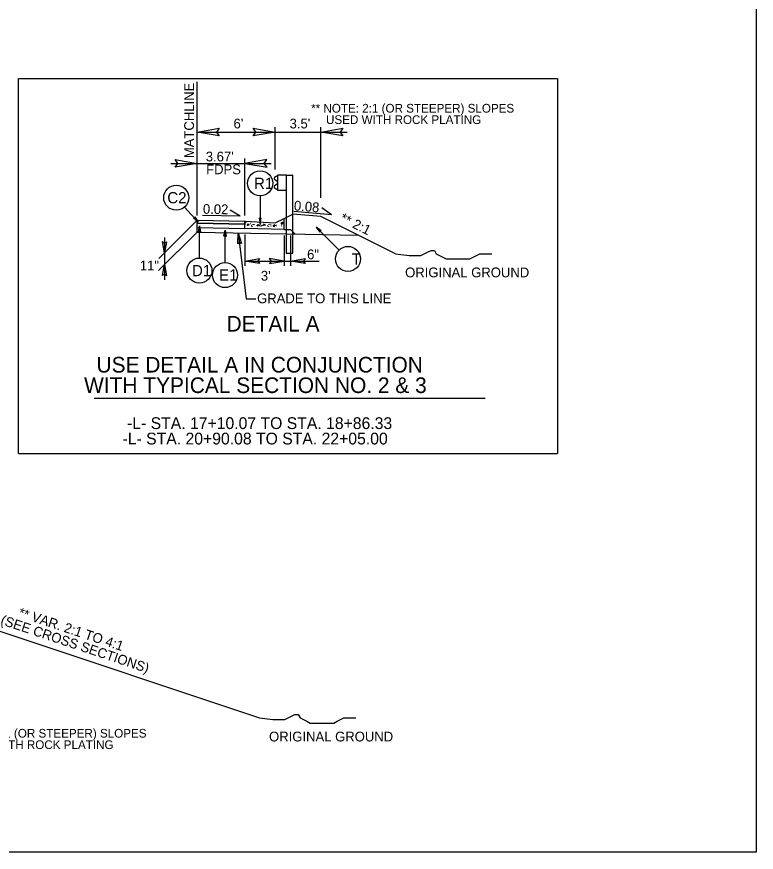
# Model space of a CAD drawing. Extents: x 1548135 to 1549339, y 868664 to 869085.
# Drawn here: x 1548249 to 1548305.7, y 868939.3 to 869003.5 of the extents above; entities that cross this region are included whole.
import ezdxf

# ---------------------------------------------------------------- set-up
doc = ezdxf.new("R2010")
doc.units = 0
for name, color, linetype in [('Default', 7, 'Continuous'), ('P_RDY_Shade_Light', 7, 'Continuous'), ('P_RDY_TC_Pvmt_Asphalt_Base_Course', 7, 'Continuous'), ('Prop Dimension', 7, 'Continuous'), ('Prop Dimension Text', 7, 'Continuous'), ('Prop Terminator CELL', 7, 'Continuous'), ('Sheet_Data_Field_CELL', 7, 'Continuous'), ('Sheet_Plan', 7, 'Continuous'), ('Typical Grade Point Symbol CELL', 7, 'Continuous'), ('Typical Hinge Slope Arterial CELL', 7, 'Continuous'), ('Typical Hinge Slope Interstate CELL', 7, 'Continuous'), ('Typical Pavement Slope Information CELL', 7, 'Continuous'), ('Typical Shoulder Slope CELL', 7, 'Continuous'), ('Typical Slope Point Local CELL', 7, 'Continuous'), ('Typical Terminator CELL', 7, 'Continuous'), ('Typical Text Centerline CELL', 7, 'Continuous'), ('Typical Text General CELL', 7, 'Continuous'), ('Typical Text Grade Point CELL', 7, 'Continuous'), ('z - Construction', 7, 'Continuous')]:
    doc.layers.add(name, color=color, linetype=linetype)

msp = doc.modelspace()

# ---------------------------------------------------------------- linework, layer by layer
at = {"layer": 'Default'}
msp.add_lwpolyline([(1548135.738, 869049.324), (1548305.738, 869049.324), (1548305.738, 868939.324), (1548135.738, 868939.324)], close=True, dxfattribs=at)
at = {"layer": 'P_RDY_Shade_Light'}
for p, q in [((1548266.481, 868987.796), (1548266.481, 868987.796)), ((1548266.481, 868987.212), (1548266.481, 868987.785)), ((1548266.492, 868987.795), (1548268.815, 868987.656)), ((1548268.815, 868987.656), (1548269.481, 868987.986)), ((1548269.481, 868987.152), (1548269.481, 868987.986)), ((1548269.481, 868987.152), (1548266.481, 868987.212)), ((1548266.659, 868987.463), (1548266.745, 868987.582)), ((1548266.78, 868987.469), (1548266.659, 868987.463)), ((1548266.745, 868987.582), (1548266.78, 868987.469)), ((1548267.425, 868987.412), (1548267.487, 868987.526)), ((1548267.59, 868987.451), (1548267.425, 868987.412)), ((1548267.487, 868987.526), (1548267.59, 868987.451)), ((1548267.909, 868987.463), (1548267.994, 868987.582)), ((1548268.029, 868987.469), (1548267.909, 868987.463)), ((1548267.994, 868987.582), (1548268.029, 868987.469)), ((1548268.673, 868987.412), (1548268.736, 868987.526)), ((1548268.839, 868987.451), (1548268.673, 868987.412)), ((1548268.736, 868987.526), (1548268.839, 868987.451)), ((1548269.251, 868987.654), (1548269.268, 868987.564)), ((1548269.405, 868987.61), (1548269.251, 868987.654)), ((1548269.268, 868987.564), (1548269.405, 868987.61))]:
    msp.add_line(p, q, dxfattribs=at)
for centre in [(1548269.377, 868987.695), (1548266.511, 868987.55), (1548266.549, 868987.675), (1548266.916, 868987.6), (1548266.976, 868987.422), (1548267.032, 868987.388), (1548267.065, 868987.515), (1548267.14, 868987.512), (1548267.191, 868987.543), (1548267.237, 868987.428), (1548267.432, 868987.467), (1548267.637, 868987.451), (1548267.654, 868987.501), (1548267.664, 868987.56), (1548267.721, 868987.417), (1548267.817, 868987.463), (1548267.911, 868987.473), (1548268.031, 868987.422), (1548268.225, 868987.422), (1548268.281, 868987.388), (1548268.314, 868987.515), (1548268.44, 868987.543), (1548268.486, 868987.428), (1548268.681, 868987.467), (1548268.709, 868987.365), (1548268.886, 868987.451), (1548268.903, 868987.501), (1548269.16, 868987.473), (1548269.28, 868987.422)]:
    msp.add_circle(centre, 0.00802, dxfattribs=at)
msp.add_arc((1548266.492, 868987.785), 0.0104, 87.95199, 180, dxfattribs=at)
at = {"layer": 'P_RDY_TC_Pvmt_Asphalt_Base_Course'}
for points in [[(1548264.499, 868994.339), (1548262.811, 868994.629), (1548264.508, 868994.929), (1548264.292, 868994.629)], [(1548267.124, 868994.92), (1548268.811, 868994.629), (1548267.114, 868994.329), (1548267.33, 868994.629)], [(1548273.999, 868994.339), (1548272.311, 868994.629), (1548274.008, 868994.929), (1548273.792, 868994.629)], [(1548261.124, 868992.513), (1548262.811, 868992.222), (1548261.114, 868991.922), (1548261.33, 868992.222)], [(1548268.169, 868992.513), (1548266.481, 868992.222), (1548268.178, 868991.922), (1548267.962, 868992.222)], [(1548267.606, 868984.526), (1548266.481, 868984.72), (1548267.612, 868984.92), (1548267.469, 868984.72)], [(1548268.356, 868984.526), (1548269.481, 868984.72), (1548268.35, 868984.92), (1548268.494, 868984.72)], [(1548271.106, 868984.526), (1548269.981, 868984.72), (1548271.112, 868984.92), (1548270.969, 868984.72)]]:
    msp.add_lwpolyline(points, close=True, dxfattribs=at)
at = {"layer": 'Prop Dimension'}
for points in [[(1548278.043, 868985.28), (1548279.08, 868985.15), (1548279.339, 868985.15), (1548279.729, 868985.15), (1548279.988, 868985.15), (1548280.248, 868985.28), (1548280.507, 868985.41), (1548280.766, 868985.54), (1548281.026, 868985.54), (1548281.156, 868985.28), (1548281.415, 868985.15), (1548281.674, 868985.02), (1548281.934, 868984.891), (1548282.193, 868984.891), (1548282.452, 868984.891), (1548282.712, 868984.891), (1548282.971, 868984.891), (1548283.23, 868984.891), (1548283.49, 868984.891), (1548283.749, 868984.891), (1548284.008, 868985.02), (1548284.268, 868985.15), (1548284.527, 868985.28), (1548284.917, 868985.28), (1548285.176, 868985.28), (1548285.435, 868985.28)], [(1548267.597, 868949.64), (1548268.635, 868949.511), (1548268.894, 868949.511), (1548269.284, 868949.511), (1548269.543, 868949.511), (1548269.802, 868949.64), (1548270.062, 868949.77), (1548270.321, 868949.9), (1548270.58, 868949.9), (1548270.71, 868949.64), (1548270.97, 868949.511), (1548271.229, 868949.381), (1548271.488, 868949.251), (1548271.748, 868949.251), (1548272.007, 868949.251), (1548272.266, 868949.251), (1548272.526, 868949.251), (1548272.785, 868949.251), (1548273.044, 868949.251), (1548273.304, 868949.251), (1548273.563, 868949.381), (1548273.822, 868949.511), (1548274.082, 868949.64), (1548274.471, 868949.64), (1548274.731, 868949.64), (1548274.99, 868949.64)]]:
    msp.add_lwpolyline(points, dxfattribs=at)
at = {"layer": 'Prop Dimension Text'}
msp.add_line((1548262.811, 868987.619), (1548266.481, 868987.546), dxfattribs=at)
at = {"layer": 'Prop Terminator CELL'}
msp.add_lwpolyline([(1548262.811, 868987.869), (1548266.481, 868987.796), (1548266.481, 868987.546), (1548262.811, 868987.619)], close=True, dxfattribs=at)
at = {"layer": 'Sheet_Data_Field_CELL'}
for p, q in [((1548269.481, 868987.986), (1548270.159, 868988.325)), ((1548278.043, 868985.28), (1548272.311, 868988.145)), ((1548238.749, 868959.256), (1548267.597, 868949.64))]:
    msp.add_line(p, q, dxfattribs=at)
at = {"layer": 'Sheet_Plan'}
msp.add_line((1548272.311, 868988.145), (1548270.159, 868988.325), dxfattribs=at)
at = {"layer": 'Typical Grade Point Symbol CELL'}
for p, q in [((1548262.811, 868988.229), (1548262.811, 868998.48)), ((1548268.811, 868991.758), (1548268.811, 868994.992)), ((1548272.311, 868989.577), (1548272.311, 868994.992)), ((1548262.811, 868994.629), (1548268.811, 868994.629)), ((1548263.811, 868994.629), (1548265.811, 868994.629)), ((1548268.811, 868994.629), (1548274.322, 868994.629)), ((1548269.811, 868994.629), (1548271.811, 868994.629)), ((1548260.801, 868992.222), (1548268.492, 868992.222)), ((1548266.481, 868988.229), (1548266.481, 868992.586)), ((1548266.481, 868986.753), (1548266.481, 868984.357)), ((1548269.481, 868986.682), (1548269.481, 868984.357)), ((1548269.981, 868986.682), (1548269.981, 868984.357)), ((1548266.481, 868984.72), (1548269.481, 868984.72)), ((1548267.462, 868984.72), (1548269.462, 868984.72)), ((1548269.481, 868984.72), (1548272.182, 868984.72))]:
    msp.add_line(p, q, dxfattribs=at)
at = {"layer": 'Typical Hinge Slope Interstate CELL'}
for p, q in [((1548267.652, 868989.728), (1548267.652, 868987.556)), ((1548261.841, 868988.861), (1548262.903, 868987.716)), ((1548259.86, 868984.918), (1548262.811, 868987.869)), ((1548262.989, 868984.952), (1548262.989, 868987.437)), ((1548264.953, 868984.605), (1548264.953, 868987.091)), ((1548273.714, 868985.564), (1548271.956, 868987.321)), ((1548259.858, 868984), (1548262.81, 868986.952)), ((1548260.306, 868986.519), (1548260.306, 868983.292)), ((1548249.097, 868969.942), (1548290.477, 868969.942))]:
    msp.add_line(p, q, dxfattribs=at)
for points in [[(1548249.097, 868969.942), (1548249.097, 868998.746), (1548290.477, 868998.746)], [(1548290.477, 868998.746), (1548290.477, 868969.942)], [(1548265.97, 868986.889), (1548266.576, 868981.812), (1548267.327, 868981.812)]]:
    msp.add_lwpolyline(points, dxfattribs=at)
for points in [[(1548262.644, 868988.114), (1548262.903, 868987.716), (1548262.521, 868988.005), (1548262.623, 868988.018)], [(1548267.571, 868988.025), (1548267.652, 868987.556), (1548267.735, 868988.027), (1548267.652, 868987.968)], [(1548262.908, 868986.969), (1548262.989, 868987.437), (1548263.072, 868986.966), (1548262.989, 868987.026)], [(1548264.872, 868986.622), (1548264.953, 868987.091), (1548265.036, 868986.619), (1548264.953, 868986.679)], [(1548272.344, 868987.047), (1548271.956, 868987.321), (1548272.23, 868986.929), (1548272.247, 868987.031)], [(1548265.926, 868986.034), (1548265.97, 868986.889), (1548266.219, 868986.065), (1548266.058, 868986.154)], [(1548260.451, 868986.208), (1548260.306, 868985.364), (1548260.156, 868986.212), (1548260.306, 868986.105)], [(1548260.161, 868983.603), (1548260.306, 868984.447), (1548260.456, 868983.599), (1548260.306, 868983.707)]]:
    msp.add_lwpolyline(points, close=True, dxfattribs=at)
for centre in [(1548267.652, 868990.69), (1548261.208, 868989.585), (1548274.393, 868984.884), (1548262.989, 868983.99), (1548264.953, 868983.644)]:
    msp.add_circle(centre, 0.962, dxfattribs=at)
at = {"layer": 'Typical Pavement Slope Information CELL'}
for p, q in [((1548266.124, 868988.16), (1548265.341, 868988.633)), ((1548273.126, 868988.28), (1548270.243, 868988.52)), ((1548273.126, 868988.28), (1548272.375, 868988.802)), ((1548266.124, 868988.16), (1548263.231, 868988.218))]:
    msp.add_line(p, q, dxfattribs=at)
at = {"layer": 'Typical Slope Point Local CELL'}
for p, q in [((1548268.887, 868991.224), (1548268.749, 868991.127)), ((1548268.75, 868990.998), (1548268.958, 868990.854)), ((1548268.987, 868991.245), (1548268.9, 868991.229)), ((1548269.659, 868991.325), (1548268.992, 868991.325)), ((1548268.992, 868991.325), (1548268.992, 868990.158)), ((1548269.659, 868991.325), (1548270.159, 868991.325)), ((1548269.675, 868991.325), (1548269.659, 868991.325)), ((1548269.659, 868991.325), (1548269.659, 868985.325)), ((1548269.675, 868985.325), (1548269.675, 868991.325)), ((1548270.159, 868991.325), (1548270.143, 868991.325)), ((1548270.143, 868991.325), (1548270.143, 868985.325)), ((1548270.159, 868985.325), (1548270.159, 868991.325)), ((1548268.749, 868990.356), (1548268.887, 868990.259)), ((1548268.958, 868990.629), (1548268.75, 868990.485)), ((1548268.992, 868990.789), (1548268.992, 868990.741)), ((1548268.992, 868990.741), (1548268.992, 868990.693)), ((1548268.9, 868990.253), (1548268.987, 868990.238)), ((1548268.992, 868990.158), (1548269.659, 868990.158)), ((1548269.659, 868985.325), (1548270.159, 868985.325)), ((1548269.659, 868985.325), (1548269.675, 868985.325)), ((1548270.143, 868985.325), (1548270.159, 868985.325))]:
    msp.add_line(p, q, dxfattribs=at)
for centre, radius, start, end in [((1548268.795, 868991.062), 0.0787, 125.2976, 235.34784), ((1548268.906, 868991.197), 0.0328, 100, 125.2976), ((1548268.795, 868990.42), 0.0787, 124.65216, 234.7024), ((1548268.913, 868990.789), 0.0787, 0.01999, 55.34784), ((1548268.913, 868990.693), 0.0787, 304.65216, 359.98001), ((1548268.906, 868990.286), 0.0328, 234.7024, 260)]:
    msp.add_arc(centre, radius, start, end, dxfattribs=at)
at = {"layer": 'Typical Terminator CELL'}
msp.add_line((1548254.916, 868974.186), (1548284.916, 868974.186), dxfattribs=at)
at = {"layer": 'Typical Text Grade Point CELL'}
for p, q in [((1548262.811, 868987.869), (1548266.481, 868987.796)), ((1548262.812, 868986.952), (1548262.811, 868987.869)), ((1548262.811, 868987.286), (1548266.481, 868987.212)), ((1548269.481, 868987.152), (1548269.982, 868987.142)), ((1548269.982, 868987.142), (1548270.316, 868986.802)), ((1548262.811, 868986.952), (1548275.192, 868986.705))]:
    msp.add_line(p, q, dxfattribs=at)

# ---------------------------------------------------------------- texts
at = {"layer": 'Sheet_Data_Field_CELL'}
for s, rotation, p in [('** 2:1', 333.49509, (1548273.718, 868987.784)), ('** VAR. 2:1 TO 4:1', 341.56503, (1548249.035, 868957.429)), ('(SEE CROSS SECTIONS)', 341.56503, (1548247.665, 868956.85))]:
    msp.add_text(s, height=0.75, rotation=rotation, dxfattribs=at).set_placement(p)
for p in [(1548278.779, 868983.475), (1548268.333, 868947.835)]:
    msp.add_text('ORIGINAL GROUND', height=0.75, dxfattribs=at).set_placement(p)
at = {"layer": 'Typical Hinge Slope Arterial CELL'}
for s, p in [('DETAIL A', (1548265.074, 868979.308)), ('  USE DETAIL A IN CONJUNCTION', (1548254.196, 868976.162)), ('  WITH TYPICAL SECTION NO. 2 & 3', (1548253.242, 868974.588))]:
    msp.add_text(s, height=1.2, dxfattribs=at).set_placement(p)
at = {"layer": 'Typical Hinge Slope Interstate CELL'}
msp.add_text('MATCHLINE', height=0.75, rotation=90, dxfattribs=at).set_placement((1548262.569, 868992.62))
for s, height, p in [('R1', 0.8608, (1548267.179, 868990.26)), ('C2', 0.8608, (1548260.522, 868989.155)), ('T', 0.861, (1548274.676, 868984.453)), ('11"', 0.75, (1548258.415, 868984.006)), ('D1', 0.8608, (1548262.416, 868983.56)), ('E1', 0.8608, (1548264.496, 868983.213)), ('GRADE TO THIS LINE', 0.75, (1548267.414, 868981.482))]:
    msp.add_text(s, height=height, dxfattribs=at).set_placement(p)
at = {"layer": 'Typical Pavement Slope Information CELL'}
msp.add_text('0.02', height=0.75, rotation=358.85436, dxfattribs=at).set_placement((1548263.251, 868988.352))
at = {"layer": 'Typical Shoulder Slope CELL'}
for s, p in [("6'", (1548265.605, 868994.904)), ("3.5'", (1548269.91, 868994.904)), ('6"', (1548271.254, 868984.861)), ("3'", (1548267.704, 868983.219))]:
    msp.add_text(s, height=0.75, dxfattribs=at).set_placement(p)
at = {"layer": 'Typical Text Centerline CELL'}
for s, p in [("3.67'", (1548263.475, 868992.372)), ('FDPS', (1548263.502, 868991.388))]:
    msp.add_text(s, height=0.75, dxfattribs=at).set_placement(p)
at = {"layer": 'Typical Text General CELL'}
for s, height, p in [('** NOTE: 2:1 (OR STEEPER) SLOPES ', 0.66824, (1548271.562, 868996.12)), ('USED WITH ROCK PLATING', 0.66824, (1548272.707, 868995.244)), ('-L- STA. 17+10.07 TO STA. 18+86.33', 0.90387, (1548257.429, 868971.823)), ('-L- STA. 20+90.08 TO STA. 22+05.00', 0.90387, (1548257.085, 868970.639)), ('** NOTE: 2:1 (OR STEEPER) SLOPES ', 0.66824, (1548243.335, 868948.129)), ('USED WITH ROCK PLATING', 0.66824, (1548244.48, 868947.253))]:
    msp.add_text(s, height=height, dxfattribs=at).set_placement(p)
at = {"layer": 'z - Construction'}
msp.add_text('0.08', height=0.75, rotation=355.23853, dxfattribs=at).set_placement((1548270.218, 868988.618))

doc.saveas('drawing.dxf')
